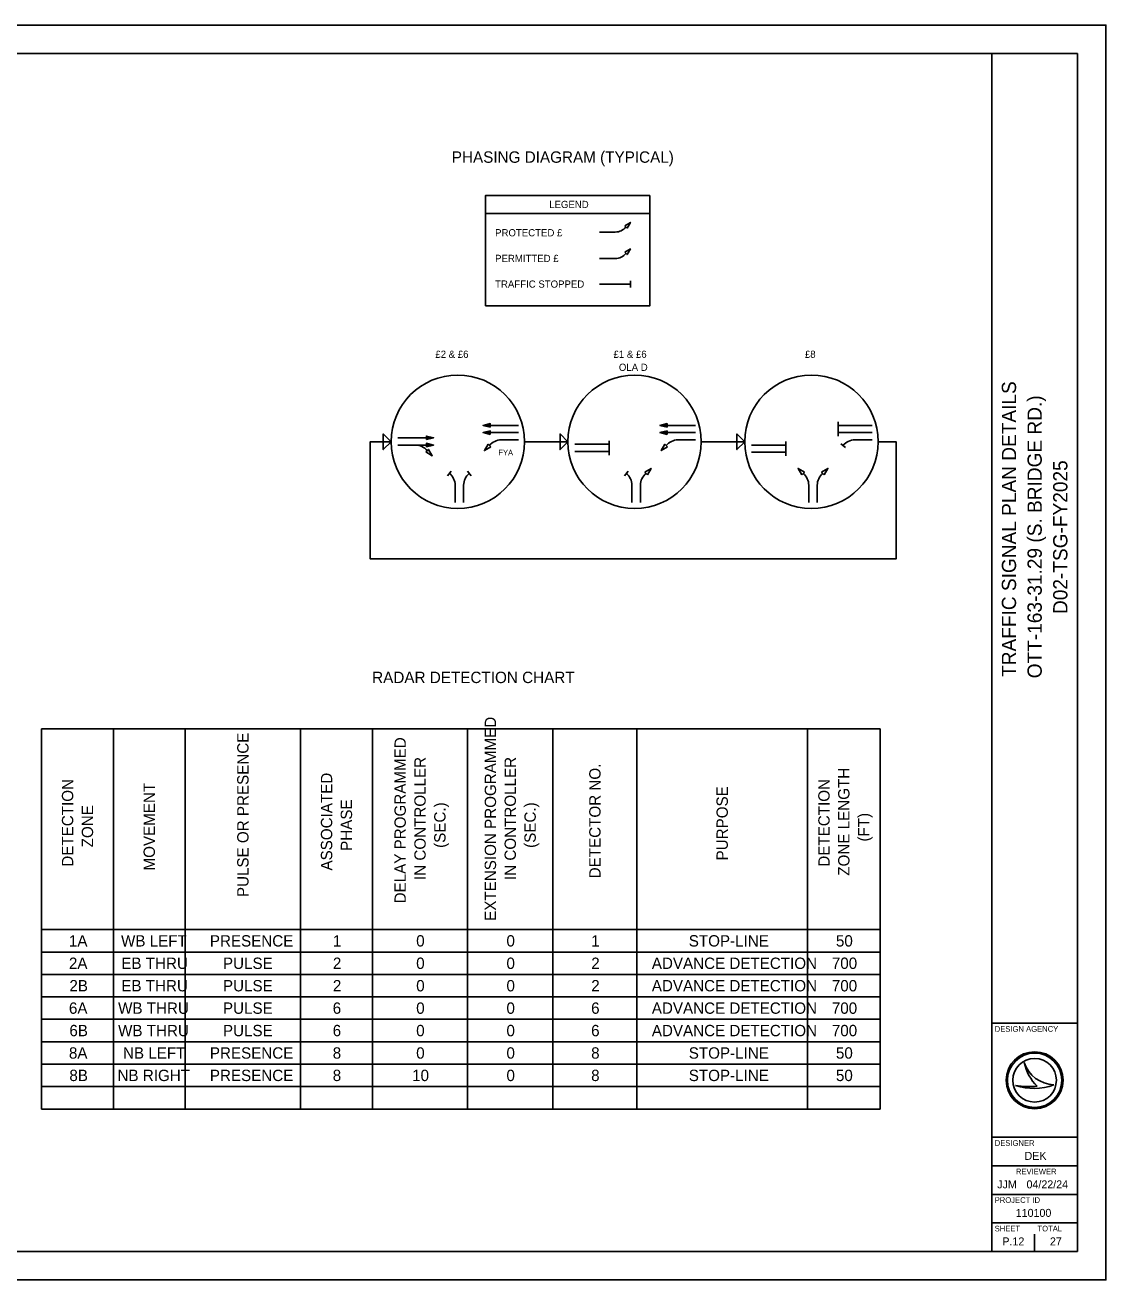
# Model space of a CAD drawing. Extents: x 0 to 680, y 0 to 440.
# Drawn here: x 300.9 to 680, y 0 to 440 of the extents above; entities that cross this region are included whole.
import ezdxf

# ---------------------------------------------------------------- set-up
doc = ezdxf.new("R2010")
doc.units = 0
for name, color, linetype in [('Default', 7, 'Continuous'), ('SH_Border', 7, 'Continuous'), ('SH_Cut_Line', 7, 'Continuous'), ('SH_Data', 7, 'Continuous'), ('SH_Text', 7, 'Continuous')]:
    doc.layers.add(name, color=color, linetype=linetype)

msp = doc.modelspace()

# ---------------------------------------------------------------- linework, layer by layer
at = {"layer": 'Default'}
for p, q in [((306.73, 193.21), (600.85, 193.21)), ((306.73, 193.21), (306.73, 59.91)), ((331.89, 193.21), (331.89, 59.91)), ((357.06, 193.21), (357.06, 59.91)), ((397.56, 193.21), (397.56, 59.91)), ((422.72, 193.21), (422.72, 59.91)), ((456.15, 193.21), (456.15, 59.91)), ((486.03, 193.21), (486.03, 59.91)), ((515.52, 193.21), (515.52, 59.91)), ((575.29, 193.21), (575.29, 59.91)), ((600.85, 193.21), (600.85, 59.91)), ((306.73, 122.82), (600.85, 122.82)), ((306.73, 114.96), (600.85, 114.96)), ((306.73, 107.09), (600.85, 107.09)), ((306.73, 99.23), (600.85, 99.23)), ((306.73, 91.37), (600.85, 91.37)), ((306.73, 83.5), (600.85, 83.5)), ((306.73, 75.64), (600.85, 75.64)), ((306.73, 67.77), (600.85, 67.77)), ((306.73, 59.91), (600.85, 59.91))]:
    msp.add_line(p, q, dxfattribs=at)
at = {"layer": 'SH_Border'}
for p, q in [((640, 10), (640, 430)), ((640, 90), (670, 90)), ((640, 50), (670, 50)), ((640, 40), (670, 40)), ((640, 30), (670, 30)), ((640, 20), (670, 20))]:
    msp.add_line(p, q, dxfattribs=at)
msp.add_lwpolyline([(30, 430), (670, 430), (670, 10), (30, 10)], close=True, dxfattribs=at)
at = {"layer": 'SH_Cut_Line'}
msp.add_lwpolyline([(0, 0), (680, 0), (680, 440), (0, 440)], close=True, dxfattribs=at)
at = {"layer": 'SH_Data'}
for p, q in [((462.45, 373.97), (520.09, 373.97)), ((502.43, 367.44), (507.93, 367.44)), ((502.43, 358.14), (507.93, 358.14)), ((502.43, 349.14), (513.24, 349.14)), ((513.24, 350.28), (513.24, 348)), ((461.57, 299.62), (474.03, 299.62)), ((523.59, 299.62), (536.04, 299.62)), ((586.05, 298.36), (586.05, 300.89)), ((598.06, 299.62), (586.05, 299.62)), ((444.17, 295.28), (431.71, 295.28)), ((461.57, 297.09), (474.03, 297.09)), ((523.59, 297.09), (536.04, 297.09)), ((586.05, 295.82), (586.05, 298.36)), ((598.06, 297.09), (586.05, 297.09)), ((444.17, 292.74), (431.71, 292.74)), ((431.71, 292.74), (437.82, 292.74)), ((474.03, 294.55), (467.92, 294.55)), ((491.31, 293.9), (476.09, 293.9)), ((493.72, 293), (505.73, 293)), ((493.72, 290.46), (505.73, 290.46)), ((505.73, 291.73), (505.73, 294.26)), ((505.73, 289.19), (505.73, 291.73)), ((536.04, 294.55), (529.93, 294.55)), ((553.33, 293.9), (538.1, 293.9)), ((555.73, 292.74), (567.75, 292.74)), ((567.75, 291.48), (567.75, 294.01)), ((567.75, 288.94), (567.75, 291.48)), ((587.02, 293.21), (588.61, 291.93)), ((598.06, 294.55), (591.95, 294.55)), ((606.42, 293.9), (606.42, 252.83)), ((555.73, 290.21), (567.75, 290.21)), ((450.41, 283.57), (449.13, 281.98)), ((456.08, 283.57), (457.36, 281.98)), ((512.42, 283.57), (511.14, 281.98)), ((451.75, 272.54), (451.75, 278.65)), ((454.74, 272.54), (454.74, 278.65)), ((513.76, 272.54), (513.76, 278.65)), ((516.75, 272.54), (516.75, 278.65)), ((575.77, 272.54), (575.77, 278.65)), ((578.76, 272.54), (578.76, 278.65)), ((651.35, 76.19), (651.35, 76.19)), ((648.34, 68.19), (648.34, 68.19)), ((655, 70), (655, 70)), ((661.75, 68.37), (661.75, 68.37)), ((647.5, 13.5), (647.5, 13.5)), ((655, 10), (655, 16))]:
    msp.add_line(p, q, dxfattribs=at)
for points in [[(520.09, 380.27), (462.45, 380.27), (462.45, 341.58), (520.09, 341.58)], [(511.25, 369.62), (513.24, 370.82), (512.04, 368.83)], [(511.25, 360.32), (513.24, 361.51), (512.04, 359.52)], [(464.07, 299), (461.57, 299.62), (464.07, 300.25)], [(526.09, 299), (523.59, 299.62), (526.09, 300.25)], [(429.3, 293.9), (426.57, 296.63), (426.57, 291.17)], [(441.67, 294.65), (444.17, 295.28), (441.67, 295.9)], [(464.07, 296.46), (461.57, 297.09), (464.07, 297.71)], [(491.31, 293.9), (488.59, 296.63), (488.58, 291.17)], [(526.09, 296.46), (523.59, 297.09), (526.09, 297.71)], [(553.33, 293.9), (550.6, 296.63), (550.6, 291.17)], [(441.51, 290.32), (443.72, 289), (442.39, 291.2)], [(441.67, 292.12), (444.17, 292.74), (441.67, 293.37)], [(464.23, 292.13), (462.02, 290.81), (463.35, 293.01)], [(526.24, 292.13), (524.03, 290.81), (525.36, 293.01)], [(519.17, 282.34), (520.5, 284.55), (518.29, 283.22)], [(573.35, 282.34), (572.03, 284.55), (574.24, 283.22)], [(581.19, 282.34), (582.51, 284.55), (580.3, 283.22)]]:
    msp.add_lwpolyline(points, close=True, dxfattribs=at)
msp.add_lwpolyline([(600.11, 293.9), (606.42, 293.9), (606.42, 252.83), (429.3, 252.84), (421.99, 252.84), (421.99, 293.9), (429.3, 293.9)], dxfattribs=at)
for centre, radius in [((452.69, 293.9), 23.39), ((514.71, 293.9), 23.39), ((576.72, 293.9), 23.39), ((655, 70), 10), ((655, 70), 9.54), ((655, 70), 9.54), ((655, 70), 7.64)]:
    msp.add_circle(centre, radius, dxfattribs=at)
for centre, radius, start, end in [((507.93, 372.21), 4.77, 270.0129, 321.2136), ((507.93, 362.91), 4.77, 270, 321.2007), ((437.82, 287.44), 5.3, 38.7864, 89.9871), ((467.92, 289.25), 5.3, 90, 141.2007), ((529.93, 289.25), 5.3, 90, 141.2007), ((591.95, 289.25), 5.3, 90.0129, 141.2136), ((446.45, 278.65), 5.3, 360, 51.2007), ((460.04, 278.65), 5.3, 128.7993, 180), ((508.46, 278.65), 5.3, 360, 51.2007), ((522.05, 278.65), 5.3, 128.7993, 180), ((570.47, 278.65), 5.3, 360, 51.2007), ((584.06, 278.65), 5.3, 128.7993, 180), ((662.32, 79.95), 11.6, 198.9257, 198.9319), ((666.93, 79.4), 15.91, 191.6379, 191.6421), ((662.32, 79.95), 11.6, 198.9319, 267.1657), ((666.93, 79.4), 15.91, 191.6421, 226.0947), ((654.79, 87.4), 20.26, 251.4576, 290.0832), ((652.96, 93.09), 25.32, 259.4964, 259.4995), ((654.79, 87.4), 20.26, 251.4527, 251.4576), ((652.96, 93.09), 25.32, 259.4995, 276.6672)]:
    msp.add_arc(centre, radius, start, end, dxfattribs=at)

# ---------------------------------------------------------------- texts
at = {"layer": 'Default'}
for s, height, p in [('EXTENSION PROGRAMMED', 3.9793, (466.11, 125.91)), ('PULSE OR PRESENCE', 3.9793, (379.3, 134.24)), ('DELAY PROGRAMMED', 3.9793, (434.46, 132.03)), (' IN CONTROLLER', 3.9793, (441.43, 138.74)), (' IN CONTROLLER', 3.9793, (473.08, 138.74)), ('DETECTOR NO.', 3.9793, (502.77, 140.82)), ('ASSOCIATED', 3.979, (408.65, 143.55)), ('ZONE LENGTH', 3.9793, (590.06, 141.73)), ('DETECTION', 3.979, (317.82, 144.9)), ('MOVEMENT', 3.979, (346.46, 143.56)), ('PURPOSE', 3.979, (547.4, 147.09)), ('DETECTION', 3.979, (583.1, 144.9)), ('PHASE', 3.979, (415.61, 150.44)), ('ZONE', 3.979, (324.78, 151.69)), ('(SEC.)', 3.979, (448.39, 151.49)), ('(SEC.)', 3.979, (480.04, 151.49)), ('(FT)', 3.979, (597.02, 153.71))]:
    msp.add_text(s, height=height, rotation=90, dxfattribs=at).set_placement(p)
for s, height, p in [('1A', 3.979, (316.3, 116.9)), ('WB LEFT', 3.979, (334.58, 116.9)), ('PRESENCE', 3.979, (365.74, 116.9)), ('1', 3.98, (408.86, 116.9)), ('0', 3.98, (438.1, 116.9)), ('0', 3.98, (469.76, 116.9)), ('1', 3.98, (499.5, 116.9)), ('STOP-LINE', 3.979, (533.7, 116.9)), ('50', 3.979, (585.31, 116.9)), ('2A', 3.979, (316.3, 109.04)), ('EB THRU', 3.979, (334.68, 109.04)), ('PULSE', 3.979, (370.33, 109.04)), ('2', 3.98, (408.87, 109.04)), ('0', 3.98, (438.1, 109.04)), ('0', 3.98, (469.76, 109.04)), ('2', 3.98, (499.5, 109.04)), ('ADVANCE DETECTION', 3.9793, (520.74, 109.04)), ('700', 3.979, (583.88, 109.04)), ('2B', 3.979, (316.47, 101.17)), ('EB THRU', 3.979, (334.68, 101.17)), ('PULSE', 3.979, (370.33, 101.17)), ('2', 3.98, (408.87, 101.17)), ('0', 3.98, (438.1, 101.17)), ('0', 3.98, (469.76, 101.17)), ('2', 3.98, (499.5, 101.17)), ('ADVANCE DETECTION', 3.9793, (520.74, 101.17)), ('700', 3.979, (583.88, 101.17)), ('6A', 3.979, (316.3, 93.31)), ('WB THRU', 3.979, (333.55, 93.31)), ('PULSE', 3.979, (370.33, 93.31)), ('6', 3.98, (408.82, 93.31)), ('0', 3.98, (438.1, 93.31)), ('0', 3.98, (469.76, 93.31)), ('6', 3.98, (499.46, 93.31)), ('ADVANCE DETECTION', 3.9793, (520.74, 93.31)), ('700', 3.979, (583.88, 93.31)), ('6B', 3.979, (316.47, 85.44)), ('WB THRU', 3.979, (333.55, 85.44)), ('PULSE', 3.979, (370.33, 85.44)), ('6', 3.98, (408.82, 85.44)), ('0', 3.98, (438.1, 85.44)), ('0', 3.98, (469.76, 85.44)), ('6', 3.98, (499.46, 85.44)), ('ADVANCE DETECTION', 3.9793, (520.74, 85.44)), ('700', 3.979, (583.88, 85.44)), ('8A', 3.979, (316.3, 77.58)), ('NB LEFT', 3.979, (335.27, 77.58)), ('PRESENCE', 3.979, (365.74, 77.58)), ('8', 3.98, (408.83, 77.58)), ('0', 3.98, (438.1, 77.58)), ('0', 3.98, (469.76, 77.58)), ('8', 3.98, (499.46, 77.58)), ('STOP-LINE', 3.979, (533.7, 77.58)), ('50', 3.979, (585.31, 77.58)), ('8B', 3.979, (316.47, 69.72)), ('NB RIGHT', 3.979, (333.35, 69.72)), ('PRESENCE', 3.979, (365.74, 69.72)), ('8', 3.98, (408.83, 69.72)), ('10', 3.979, (436.67, 69.72)), ('0', 3.98, (469.76, 69.72)), ('8', 3.98, (499.46, 69.72)), ('STOP-LINE', 3.979, (533.7, 69.72)), ('50', 3.979, (585.31, 69.72))]:
    msp.add_text(s, height=height, dxfattribs=at).set_placement(p)
at = {"layer": 'SH_Data'}
for s, p in [('TRAFFIC SIGNAL PLAN DETAILS', (648.5, 211.45)), ('OTT-163-31.29 (S. BRIDGE RD.)', (657.5, 210.96)), ('D02-TSG-FY2025', (666.5, 233.5))]:
    msp.add_text(s, height=5, rotation=90, dxfattribs=at).set_placement(p)
for s, height, p in [('DESIGN AGENCY', 2, (641, 87)), ('DESIGNER', 2, (641, 47)), ('DEK', 2.8, (651.47, 42.1)), ('REVIEWER', 2, (648.44, 37)), ('JJM', 2.8, (641.89, 32.1)), ('04/22/24', 2.8, (652.16, 32.1)), ('PROJECT ID', 2, (641, 27)), ('110100', 2.8, (648.37, 22.1)), ('SHEET', 2, (641, 17)), ('TOTAL', 2, (656, 17)), ('P.12', 2.8, (643.69, 12.1)), ('27', 2.8, (660.37, 12.1))]:
    msp.add_text(s, height=height, dxfattribs=at).set_placement(p)
at = {"layer": 'SH_Text'}
for s, height, p in [('PHASING DIAGRAM (TYPICAL)', 4, (450.59, 391.72)), ('LEGEND', 2.52, (484.74, 375.86)), ('PROTECTED £', 2.52, (465.78, 365.93)), ('PERMITTED £', 2.52, (465.78, 356.93)), ('TRAFFIC STOPPED', 2.52, (465.78, 347.93)), ('£2 & £6', 2.52, (444.82, 323.32)), ('£1 & £6', 2.52, (507.31, 323.32)), ('£8', 2.52, (574.43, 323.32)), ('OLA D', 2.52, (509.18, 318.75)), ('FYA', 1.974, (466.94, 289.12)), ('RADAR DETECTION CHART', 4, (422.65, 209.27))]:
    msp.add_text(s, height=height, dxfattribs=at).set_placement(p)

doc.saveas('drawing.dxf')
